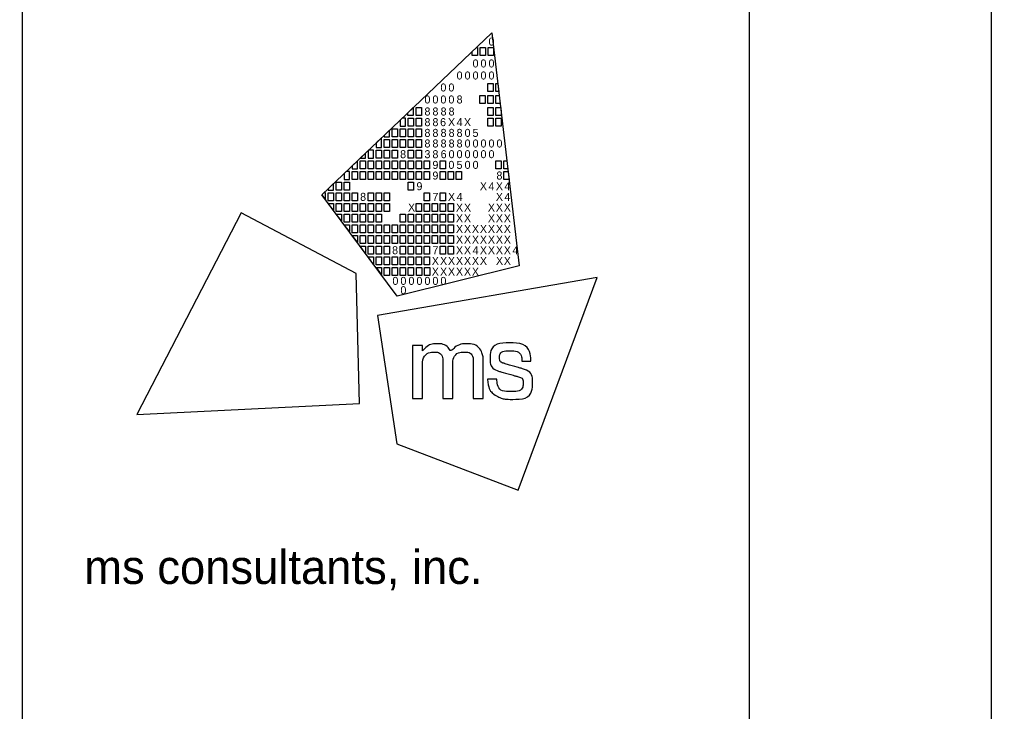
# Model space of a CAD drawing. Extents: x 0 to 34, y 0 to 22.
# Drawn here: x 31.994 to 34, y 2.686 to 4.114 of the extents above; entities that cross this region are included whole.
import ezdxf

# ---------------------------------------------------------------- set-up
doc = ezdxf.new("R2010")
doc.units = 0
for name, color, linetype in [('SH_Border', 7, 'Continuous'), ('SH_Cut_Line', 7, 'Continuous'), ('SH_Data', 7, 'Continuous')]:
    doc.layers.add(name, color=color, linetype=linetype)

msp = doc.modelspace()

# ---------------------------------------------------------------- linework, layer by layer
at = {"layer": 'SH_Border'}
msp.add_line((32, 0.5), (32, 21.5), dxfattribs=at)
msp.add_lwpolyline([(1.5, 21.5), (33.5, 21.5), (33.5, 0.5), (1.5, 0.5)], close=True, dxfattribs=at)
at = {"layer": 'SH_Cut_Line'}
msp.add_lwpolyline([(0, 0), (34, 0), (34, 22), (0, 22)], close=True, dxfattribs=at)
at = {"layer": 'SH_Data'}
for p, q in [((32.6175, 3.7519), (32.9688, 4.0861)), ((32.9688, 4.0861), (32.9688, 4.0861)), ((32.9688, 4.0861), (33.0253, 3.6052)), ((32.773, 3.543), (32.6175, 3.7519)), ((33.0253, 3.6052), (32.773, 3.543)), ((32.75, 3.5), (32.75, 3.5))]:
    msp.add_line(p, q, dxfattribs=at)
for points in [[(32.9279, 4.0472), (32.9369, 4.0558), (32.9389, 4.0558), (32.9389, 4.0393), (32.9279, 4.0393)], [(32.9444, 4.0558), (32.9554, 4.0558), (32.9554, 4.0393), (32.9444, 4.0393)], [(32.9609, 4.0558), (32.9719, 4.0558), (32.9719, 4.0393), (32.9609, 4.0393)], [(32.9606, 3.9815), (32.9716, 3.9815), (32.9716, 3.965), (32.9606, 3.965)], [(32.9771, 3.9815), (32.9811, 3.9815), (32.983, 3.965), (32.9771, 3.965)], [(32.9441, 3.9567), (32.9551, 3.9567), (32.9551, 3.9402), (32.9441, 3.9402)], [(32.9606, 3.9567), (32.9716, 3.9567), (32.9716, 3.9402), (32.9606, 3.9402)], [(32.9771, 3.9567), (32.984, 3.9567), (32.9859, 3.9402), (32.9771, 3.9402)], [(32.7953, 3.9211), (32.8064, 3.9316), (32.8064, 3.9154), (32.7953, 3.9154)], [(32.8123, 3.9319), (32.8233, 3.9319), (32.8233, 3.9154), (32.8123, 3.9154)], [(32.9606, 3.9319), (32.9716, 3.9319), (32.9716, 3.9154), (32.9606, 3.9154)], [(32.9771, 3.9319), (32.9869, 3.9319), (32.9881, 3.9218), (32.9881, 3.9154), (32.9771, 3.9154)], [(32.7958, 3.9099), (32.8068, 3.9099), (32.8068, 3.8934), (32.7958, 3.8934)], [(32.8123, 3.9099), (32.8233, 3.9099), (32.8233, 3.8934), (32.8123, 3.8934)], [(32.9606, 3.9099), (32.9716, 3.9099), (32.9716, 3.8934), (32.9606, 3.8934)], [(32.9771, 3.9099), (32.9881, 3.9099), (32.9881, 3.8934), (32.9771, 3.8934)], [(32.7627, 3.8879), (32.7737, 3.8879), (32.7737, 3.8714), (32.7627, 3.8714)], [(32.7793, 3.8879), (32.7903, 3.8879), (32.7903, 3.8714), (32.7793, 3.8714)], [(32.7958, 3.8879), (32.8068, 3.8879), (32.8068, 3.8714), (32.7958, 3.8714)], [(32.8123, 3.8879), (32.8233, 3.8879), (32.8233, 3.8714), (32.8123, 3.8714)], [(32.7462, 3.8659), (32.7572, 3.8659), (32.7572, 3.8494), (32.7462, 3.8494)], [(32.7627, 3.8659), (32.7737, 3.8659), (32.7737, 3.8494), (32.7627, 3.8494)], [(32.7793, 3.8659), (32.7903, 3.8659), (32.7903, 3.8494), (32.7793, 3.8494)], [(32.7958, 3.8659), (32.8068, 3.8659), (32.8068, 3.8494), (32.7958, 3.8494)], [(32.8123, 3.8659), (32.8233, 3.8659), (32.8233, 3.8494), (32.8123, 3.8494)], [(32.7297, 3.8439), (32.7407, 3.8439), (32.7407, 3.8273), (32.7297, 3.8273)], [(32.7462, 3.8439), (32.7572, 3.8439), (32.7572, 3.8273), (32.7462, 3.8273)], [(32.7627, 3.8439), (32.7737, 3.8439), (32.7737, 3.8273), (32.7627, 3.8273)], [(32.7958, 3.8439), (32.8068, 3.8439), (32.8068, 3.8273), (32.7958, 3.8273)], [(32.8123, 3.8439), (32.8233, 3.8439), (32.8233, 3.8273), (32.8123, 3.8273)], [(32.6967, 3.8218), (32.7077, 3.8218), (32.7077, 3.8053), (32.6967, 3.8053)], [(32.7132, 3.8218), (32.7242, 3.8218), (32.7242, 3.8053), (32.7132, 3.8053)], [(32.7297, 3.8218), (32.7407, 3.8218), (32.7407, 3.8053), (32.7297, 3.8053)], [(32.7462, 3.8218), (32.7572, 3.8218), (32.7572, 3.8053), (32.7462, 3.8053)], [(32.7627, 3.8218), (32.7737, 3.8218), (32.7737, 3.8053), (32.7627, 3.8053)], [(32.7793, 3.8218), (32.7903, 3.8218), (32.7903, 3.8053), (32.7793, 3.8053)], [(32.7958, 3.8218), (32.8068, 3.8218), (32.8068, 3.8053), (32.7958, 3.8053)], [(32.8123, 3.8218), (32.8233, 3.8218), (32.8233, 3.8053), (32.8123, 3.8053)], [(32.8288, 3.8218), (32.8398, 3.8218), (32.8398, 3.8053), (32.8288, 3.8053)], [(32.8618, 3.8218), (32.8728, 3.8218), (32.8728, 3.8053), (32.8618, 3.8053)], [(32.9771, 3.8218), (32.9881, 3.8218), (32.9881, 3.8053), (32.9771, 3.8053)], [(32.9935, 3.8218), (32.9998, 3.8218), (33.0018, 3.8053), (32.9935, 3.8053)], [(32.6802, 3.7998), (32.6912, 3.7998), (32.6912, 3.7833), (32.6802, 3.7833)], [(32.6967, 3.7998), (32.7077, 3.7998), (32.7077, 3.7833), (32.6967, 3.7833)], [(32.7132, 3.7998), (32.7242, 3.7998), (32.7242, 3.7833), (32.7132, 3.7833)], [(32.7297, 3.7998), (32.7407, 3.7998), (32.7407, 3.7833), (32.7297, 3.7833)], [(32.7462, 3.7998), (32.7572, 3.7998), (32.7572, 3.7833), (32.7462, 3.7833)], [(32.7627, 3.7998), (32.7737, 3.7998), (32.7737, 3.7833), (32.7627, 3.7833)], [(32.7793, 3.7998), (32.7903, 3.7998), (32.7903, 3.7833), (32.7793, 3.7833)], [(32.7958, 3.7998), (32.8068, 3.7998), (32.8068, 3.7833), (32.7958, 3.7833)], [(32.8123, 3.7998), (32.8233, 3.7998), (32.8233, 3.7833), (32.8123, 3.7833)], [(32.8288, 3.7998), (32.8398, 3.7998), (32.8398, 3.7833), (32.8288, 3.7833)], [(32.8618, 3.7998), (32.8728, 3.7998), (32.8728, 3.7833), (32.8618, 3.7833)], [(32.8783, 3.7998), (32.8893, 3.7998), (32.8893, 3.7833), (32.8783, 3.7833)], [(32.8947, 3.7998), (32.9057, 3.7998), (32.9057, 3.7833), (32.8947, 3.7833)], [(32.9935, 3.7998), (33.0024, 3.7998), (33.0044, 3.7833), (32.9935, 3.7833)], [(32.6471, 3.7778), (32.6581, 3.7778), (32.6581, 3.7613), (32.6471, 3.7613)], [(32.6637, 3.7778), (32.6747, 3.7778), (32.6747, 3.7613), (32.6637, 3.7613)], [(32.7958, 3.7778), (32.8068, 3.7778), (32.8068, 3.7613), (32.7958, 3.7613)], [(32.6306, 3.7558), (32.6416, 3.7558), (32.6416, 3.7393), (32.6306, 3.7393)], [(32.6471, 3.7558), (32.6581, 3.7558), (32.6581, 3.7393), (32.6471, 3.7393)], [(32.6637, 3.7558), (32.6747, 3.7558), (32.6747, 3.7393), (32.6637, 3.7393)], [(32.6802, 3.7558), (32.6912, 3.7558), (32.6912, 3.7393), (32.6802, 3.7393)], [(32.7132, 3.7558), (32.7242, 3.7558), (32.7242, 3.7393), (32.7132, 3.7393)], [(32.7297, 3.7558), (32.7407, 3.7558), (32.7407, 3.7393), (32.7297, 3.7393)], [(32.7462, 3.7558), (32.7572, 3.7558), (32.7572, 3.7393), (32.7462, 3.7393)], [(32.8288, 3.7558), (32.8398, 3.7558), (32.8398, 3.7393), (32.8288, 3.7393)], [(32.8618, 3.7558), (32.8728, 3.7558), (32.8728, 3.7393), (32.8618, 3.7393)], [(32.6306, 3.7338), (32.6416, 3.7338), (32.6416, 3.72)], [(32.6471, 3.7338), (32.6581, 3.7338), (32.6581, 3.7173), (32.6471, 3.7173)], [(32.6637, 3.7338), (32.6747, 3.7338), (32.6747, 3.7173), (32.6637, 3.7173)], [(32.6802, 3.7338), (32.6912, 3.7338), (32.6912, 3.7173), (32.6802, 3.7173)], [(32.6967, 3.7338), (32.7077, 3.7338), (32.7077, 3.7173), (32.6967, 3.7173)], [(32.7132, 3.7338), (32.7242, 3.7338), (32.7242, 3.7173), (32.7132, 3.7173)], [(32.7297, 3.7338), (32.7407, 3.7338), (32.7407, 3.7173), (32.7297, 3.7173)], [(32.7462, 3.7338), (32.7572, 3.7338), (32.7572, 3.7173), (32.7462, 3.7173)], [(32.8123, 3.7338), (32.8233, 3.7338), (32.8233, 3.7173), (32.8123, 3.7173)], [(32.8288, 3.7338), (32.8398, 3.7338), (32.8398, 3.7173), (32.8288, 3.7173)], [(32.8453, 3.7338), (32.8563, 3.7338), (32.8563, 3.7173), (32.8453, 3.7173)], [(32.8618, 3.7338), (32.8728, 3.7338), (32.8728, 3.7173), (32.8618, 3.7173)], [(32.8783, 3.7338), (32.8893, 3.7338), (32.8893, 3.7173), (32.8783, 3.7173)], [(32.6471, 3.7117), (32.6581, 3.7117), (32.6581, 3.698)], [(32.6637, 3.7117), (32.6747, 3.7117), (32.6747, 3.6952), (32.6637, 3.6952)], [(32.6802, 3.7117), (32.6912, 3.7117), (32.6912, 3.6952), (32.6802, 3.6952)], [(32.6967, 3.7117), (32.7077, 3.7117), (32.7077, 3.6952), (32.6967, 3.6952)], [(32.7132, 3.7117), (32.7242, 3.7117), (32.7242, 3.6952), (32.7132, 3.6952)], [(32.7297, 3.7117), (32.7407, 3.7117), (32.7407, 3.6952), (32.7297, 3.6952)], [(32.7793, 3.7117), (32.7903, 3.7117), (32.7903, 3.6952), (32.7793, 3.6952)], [(32.7958, 3.7117), (32.8068, 3.7117), (32.8068, 3.6952), (32.7958, 3.6952)], [(32.8123, 3.7117), (32.8233, 3.7117), (32.8233, 3.6952), (32.8123, 3.6952)], [(32.8288, 3.7117), (32.8398, 3.7117), (32.8398, 3.6952), (32.8288, 3.6952)], [(32.8453, 3.7117), (32.8563, 3.7117), (32.8563, 3.6952), (32.8453, 3.6952)], [(32.8618, 3.7117), (32.8728, 3.7117), (32.8728, 3.6952), (32.8618, 3.6952)], [(32.8783, 3.7117), (32.8893, 3.7117), (32.8893, 3.6952), (32.8783, 3.6952)], [(32.6637, 3.6897), (32.6747, 3.6897), (32.6747, 3.676)], [(32.6747, 3.6897), (32.6747, 3.6897), (32.6747, 3.6897)], [(32.6802, 3.6897), (32.6912, 3.6897), (32.6912, 3.6732), (32.6802, 3.6732)], [(32.6967, 3.6897), (32.7077, 3.6897), (32.7077, 3.6732), (32.6967, 3.6732)], [(32.7132, 3.6897), (32.7242, 3.6897), (32.7242, 3.6732), (32.7132, 3.6732)], [(32.7297, 3.6897), (32.7407, 3.6897), (32.7407, 3.6732), (32.7297, 3.6732)], [(32.7462, 3.6897), (32.7572, 3.6897), (32.7572, 3.6732), (32.7462, 3.6732)], [(32.7627, 3.6897), (32.7737, 3.6897), (32.7737, 3.6732), (32.7627, 3.6732)], [(32.7793, 3.6897), (32.7903, 3.6897), (32.7903, 3.6732), (32.7793, 3.6732)], [(32.7958, 3.6897), (32.8068, 3.6897), (32.8068, 3.6732), (32.7958, 3.6732)], [(32.8123, 3.6897), (32.8233, 3.6897), (32.8233, 3.6732), (32.8123, 3.6732)], [(32.8288, 3.6897), (32.8398, 3.6897), (32.8398, 3.6732), (32.8288, 3.6732)], [(32.8453, 3.6897), (32.8563, 3.6897), (32.8563, 3.6732), (32.8453, 3.6732)], [(32.8618, 3.6897), (32.8728, 3.6897), (32.8728, 3.6732), (32.8618, 3.6732)], [(32.8783, 3.6897), (32.8893, 3.6897), (32.8893, 3.6732), (32.8783, 3.6732)], [(32.6802, 3.6677), (32.6912, 3.6677), (32.6912, 3.654)], [(32.6967, 3.6677), (32.7077, 3.6677), (32.7077, 3.6512), (32.6967, 3.6512)], [(32.7132, 3.6677), (32.7242, 3.6677), (32.7242, 3.6512), (32.7132, 3.6512)], [(32.7297, 3.6677), (32.7407, 3.6677), (32.7407, 3.6512), (32.7297, 3.6512)], [(32.7462, 3.6677), (32.7572, 3.6677), (32.7572, 3.6512), (32.7462, 3.6512)], [(32.7627, 3.6677), (32.7737, 3.6677), (32.7737, 3.6512), (32.7627, 3.6512)], [(32.7793, 3.6677), (32.7903, 3.6677), (32.7903, 3.6512), (32.7793, 3.6512)], [(32.7958, 3.6677), (32.8068, 3.6677), (32.8068, 3.6512), (32.7958, 3.6512)], [(32.8123, 3.6677), (32.8233, 3.6677), (32.8233, 3.6512), (32.8123, 3.6512)], [(32.8288, 3.6677), (32.8398, 3.6677), (32.8398, 3.6512), (32.8288, 3.6512)], [(32.8453, 3.6677), (32.8563, 3.6677), (32.8563, 3.6512), (32.8453, 3.6512)], [(32.8618, 3.6677), (32.8728, 3.6677), (32.8728, 3.6512), (32.8618, 3.6512)], [(32.8783, 3.6677), (32.8893, 3.6677), (32.8893, 3.6512), (32.8783, 3.6512)], [(32.7077, 3.6305), (32.6965, 3.6457), (32.7077, 3.6457)], [(32.7132, 3.6457), (32.7242, 3.6457), (32.7242, 3.6292), (32.7132, 3.6292)], [(32.7297, 3.6457), (32.7407, 3.6457), (32.7407, 3.6292), (32.7297, 3.6292)], [(32.7462, 3.6457), (32.7572, 3.6457), (32.7572, 3.6292), (32.7462, 3.6292)], [(32.7793, 3.6457), (32.7903, 3.6457), (32.7903, 3.6292), (32.7793, 3.6292)], [(32.7958, 3.6457), (32.8068, 3.6457), (32.8068, 3.6292), (32.7958, 3.6292)], [(32.8123, 3.6457), (32.8233, 3.6457), (32.8233, 3.6292), (32.8123, 3.6292)], [(32.8288, 3.6457), (32.8398, 3.6457), (32.8398, 3.6292), (32.8288, 3.6292)], [(32.8618, 3.6457), (32.8728, 3.6457), (32.8728, 3.6292), (32.8618, 3.6292)], [(32.8783, 3.6457), (32.8893, 3.6457), (32.8893, 3.6292), (32.8783, 3.6292)], [(32.724, 3.6082), (32.7132, 3.6237), (32.7242, 3.6237)], [(32.7297, 3.6237), (32.7407, 3.6237), (32.7407, 3.6072), (32.7297, 3.6072)], [(32.7462, 3.6237), (32.7572, 3.6237), (32.7572, 3.6072), (32.7462, 3.6072)], [(32.7627, 3.6237), (32.7737, 3.6237), (32.7737, 3.6072), (32.7627, 3.6072)], [(32.7793, 3.6237), (32.7903, 3.6237), (32.7903, 3.6072), (32.7793, 3.6072)], [(32.7958, 3.6237), (32.8068, 3.6237), (32.8068, 3.6072), (32.7958, 3.6072)], [(32.8123, 3.6237), (32.8233, 3.6237), (32.8233, 3.6072), (32.8123, 3.6072)], [(32.8288, 3.6237), (32.8398, 3.6237), (32.8398, 3.6072), (32.8288, 3.6072)], [(32.7302, 3.6017), (32.7407, 3.6017), (32.7408, 3.5875)], [(32.7463, 3.6017), (32.7573, 3.6017), (32.7573, 3.5852), (32.7463, 3.5852)], [(32.763, 3.6017), (32.774, 3.6017), (32.774, 3.5852), (32.763, 3.5852)], [(32.7794, 3.6017), (32.7904, 3.6017), (32.7904, 3.5852), (32.7794, 3.5852)], [(32.796, 3.6017), (32.807, 3.6017), (32.807, 3.5852), (32.796, 3.5852)], [(32.8129, 3.6017), (32.8239, 3.6017), (32.8239, 3.5851), (32.8129, 3.5851)], [(32.8296, 3.6017), (32.8406, 3.6017), (32.8406, 3.5851), (32.8296, 3.5851)]]:
    msp.add_lwpolyline(points, close=True, dxfattribs=at)
for points in [[(32.7903, 3.9099), (32.7836, 3.9099), (32.7793, 3.9058), (32.7793, 3.8934), (32.7903, 3.8934), (32.7903, 3.9099)], [(32.7572, 3.8849), (32.7462, 3.8744), (32.7462, 3.8714), (32.7572, 3.8714), (32.7572, 3.8849)], [(32.7407, 3.8691), (32.7297, 3.8587), (32.7297, 3.8494), (32.7407, 3.8494), (32.7407, 3.8691)], [(32.7077, 3.8377), (32.6968, 3.8273), (32.7077, 3.8273), (32.7077, 3.8377)], [(32.7242, 3.8439), (32.7141, 3.8439), (32.7132, 3.843), (32.7132, 3.8273), (32.7242, 3.8273), (32.7242, 3.8439)], [(32.6912, 3.822), (32.6802, 3.8115), (32.6802, 3.8053), (32.6912, 3.8053), (32.6912, 3.822)], [(32.6747, 3.7998), (32.6679, 3.7998), (32.6637, 3.7958), (32.6637, 3.7833), (32.6747, 3.7833), (32.6747, 3.7998)], [(32.6416, 3.7749), (32.6306, 3.7644), (32.6306, 3.7613), (32.6416, 3.7613), (32.6416, 3.7749)], [(32.6251, 3.7558), (32.6216, 3.7558), (32.6175, 3.7519), (32.6251, 3.7417), (32.6251, 3.7558)], [(32.4512, 3.7149), (32.2359, 3.2988), (32.6956, 3.3215), (32.6884, 3.5892), (32.4512, 3.7149)], [(33.0229, 3.1422), (33.1859, 3.5814), (32.7324, 3.5029), (32.7722, 3.2381), (33.0229, 3.1422)]]:
    msp.add_lwpolyline(points, dxfattribs=at)
for points in [[(32.8048, 3.3315), (32.8048, 3.3315), (32.8048, 3.4409), (32.8048, 3.4409), (32.8048, 3.4409), (32.8255, 3.4409), (32.8255, 3.4409), (32.8255, 3.4409), (32.8255, 3.4297), (32.8255, 3.4297), (32.8346, 3.4399), (32.8457, 3.4445), (32.8555, 3.4445), (32.8688, 3.4445), (32.8791, 3.4372), (32.8837, 3.4266), (32.8915, 3.4381), (32.905, 3.4446), (32.9166, 3.4446), (32.9325, 3.4446), (32.9451, 3.435), (32.9494, 3.4213), (32.9494, 3.4212), (32.9494, 3.4212), (32.9494, 3.4212), (32.9501, 3.419), (32.9506, 3.4172), (32.9506, 3.4071), (32.9506, 3.4071), (32.9506, 3.3314), (32.9506, 3.3314), (32.9506, 3.3314), (32.9303, 3.3314), (32.9303, 3.3314), (32.9303, 3.3314), (32.9303, 3.4048), (32.9303, 3.4048), (32.9303, 3.4201), (32.9219, 3.4274), (32.911, 3.4274), (32.8995, 3.4274), (32.8879, 3.4171), (32.8879, 3.4001), (32.8879, 3.4001), (32.8879, 3.3315), (32.8879, 3.3315), (32.8879, 3.3315), (32.8674, 3.3315), (32.8674, 3.3315), (32.8674, 3.3315), (32.8674, 3.4059), (32.8674, 3.4059), (32.8674, 3.4203), (32.8588, 3.4274), (32.8496, 3.4274), (32.8384, 3.4274), (32.8254, 3.417), (32.8254, 3.3962), (32.8254, 3.3962), (32.8254, 3.3315), (32.8254, 3.3315), (32.8254, 3.3315), (32.8048, 3.3315), (32.8048, 3.3315)], [(32.9595, 3.3709), (32.9595, 3.3709), (32.9595, 3.3717), (32.9595, 3.3717), (32.9595, 3.3717), (32.9603, 3.3717), (32.9603, 3.3717), (32.9603, 3.3717), (32.9783, 3.3717), (32.9783, 3.3717), (32.9783, 3.3717), (32.9789, 3.3717), (32.9789, 3.3717), (32.9789, 3.3717), (32.979, 3.371), (32.979, 3.371), (32.9803, 3.3554), (32.9887, 3.346), (33.009, 3.346), (33.0273, 3.346), (33.0333, 3.3554), (33.0333, 3.3631), (33.0333, 3.3732), (33.0256, 3.3758), (33.0175, 3.378), (33.0175, 3.378), (32.987, 3.3867), (32.987, 3.3867), (32.972, 3.3909), (32.9648, 3.4019), (32.9648, 3.4142), (32.9648, 3.4303), (32.9768, 3.4462), (33.0052, 3.4462), (33.0348, 3.4462), (33.0489, 3.4285), (33.0489, 3.4095), (33.0489, 3.4095), (33.0489, 3.4087), (33.0489, 3.4087), (33.0489, 3.4087), (33.0482, 3.4087), (33.0482, 3.4087), (33.0482, 3.4087), (33.0312, 3.4087), (33.0312, 3.4087), (33.0312, 3.4087), (33.0305, 3.4087), (33.0305, 3.4087), (33.0305, 3.4087), (33.0305, 3.4094), (33.0305, 3.4094), (33.0301, 3.4208), (33.0226, 3.43), (33.0056, 3.43), (32.9891, 3.43), (32.9843, 3.4218), (32.9843, 3.4157), (32.9843, 3.4108), (32.9869, 3.4059), (32.9959, 3.4033), (32.9959, 3.4033), (33.0255, 3.3948), (33.0255, 3.3948), (33.0462, 3.3889), (33.0527, 3.3777), (33.0527, 3.3639), (33.0527, 3.3462), (33.041, 3.3298), (33.0087, 3.3298), (32.9952, 3.3298), (32.9877, 3.3321), (32.9823, 3.3348), (32.969, 3.3414), (32.9609, 3.3536), (32.9595, 3.3709)]]:
    msp.add_open_spline(points, degree=3, dxfattribs=at)

# ---------------------------------------------------------------- texts
for s, height, p in [('0', 0.0165, (32.9617, 4.0597)), ('0', 0.0165, (32.9288, 4.0145)), ('0', 0.0165, (32.9452, 4.0145)), ('0', 0.0165, (32.9617, 4.0145)), ('0', 0.0165, (32.8958, 3.9897)), ('0', 0.0165, (32.9123, 3.9897)), ('0', 0.0165, (32.9288, 3.9897)), ('0', 0.0165, (32.9452, 3.9897)), ('0', 0.0165, (32.9617, 3.9897)), ('0', 0.0165, (32.8625, 3.965)), ('0', 0.0165, (32.879, 3.965)), ('0', 0.0165, (32.8295, 3.9402)), ('0', 0.0165, (32.846, 3.9402)), ('0', 0.0165, (32.8625, 3.9402)), ('0', 0.0165, (32.879, 3.9402)), ('8', 0.0165, (32.8958, 3.9402)), ('8', 0.0165, (32.8295, 3.9154)), ('8', 0.0165, (32.846, 3.9154)), ('8', 0.0165, (32.8628, 3.9154)), ('8', 0.0165, (32.8793, 3.9154)), ('8', 0.0165, (32.8295, 3.8934)), ('8', 0.0165, (32.846, 3.8934)), ('6', 0.0165, (32.8618, 3.8934)), ('X', 0.0165, (32.8781, 3.8934)), ('4', 0.0165, (32.8958, 3.8934)), ('X', 0.0165, (32.911, 3.8934)), ('8', 0.0165, (32.8295, 3.8713)), ('8', 0.0165, (32.846, 3.8713)), ('8', 0.0165, (32.8628, 3.8713)), ('8', 0.0165, (32.8794, 3.8713)), ('8', 0.0165, (32.8958, 3.8713)), ('0', 0.0165, (32.9123, 3.8713)), ('5', 0.0165, (32.9287, 3.8713)), ('8', 0.0165, (32.8295, 3.8494)), ('8', 0.0165, (32.846, 3.8494)), ('8', 0.0165, (32.8628, 3.8494)), ('8', 0.0165, (32.8794, 3.8494)), ('8', 0.0165, (32.8958, 3.8494)), ('0', 0.0165, (32.9123, 3.8494)), ('0', 0.0165, (32.9288, 3.8494)), ('0', 0.0165, (32.9452, 3.8494)), ('0', 0.0165, (32.9617, 3.8494)), ('0', 0.0165, (32.9782, 3.8494)), ('8', 0.0165, (32.7793, 3.8273)), ('3', 0.0165, (32.8295, 3.8273)), ('8', 0.0165, (32.846, 3.8273)), ('6', 0.0165, (32.8629, 3.8273)), ('0', 0.0165, (32.8793, 3.8273)), ('0', 0.0165, (32.8958, 3.8273)), ('0', 0.0165, (32.9123, 3.8273)), ('0', 0.0165, (32.9288, 3.8273)), ('0', 0.0165, (32.9452, 3.8273)), ('0', 0.0165, (32.9617, 3.8273)), ('9', 0.0165, (32.846, 3.8053)), ('0', 0.0165, (32.879, 3.8053)), ('5', 0.0165, (32.8957, 3.8053)), ('0', 0.0165, (32.9123, 3.8053)), ('0', 0.0165, (32.9288, 3.8053)), ('9', 0.0165, (32.846, 3.7833)), ('8', 0.0165, (32.9781, 3.7833)), ('9', 0.0165, (32.813, 3.7613)), ('X', 0.0165, (32.9439, 3.7613)), ('4', 0.0165, (32.9617, 3.7613)), ('X', 0.0165, (32.9769, 3.7613)), ('4', 0.0165, (32.9946, 3.7613)), ('8', 0.0165, (32.6967, 3.7393)), ('7', 0.0165, (32.846, 3.7393)), ('X', 0.0165, (32.8781, 3.7393)), ('4', 0.0165, (32.8958, 3.7393)), ('X', 0.0165, (32.9769, 3.7393)), ('4', 0.0165, (32.9946, 3.7393)), ('X', 0.0165, (32.7955, 3.7173)), ('X', 0.0165, (32.8945, 3.7173)), ('X', 0.0165, (32.911, 3.7173)), ('X', 0.0165, (32.9604, 3.7173)), ('X', 0.0165, (32.9769, 3.7173)), ('X', 0.0165, (32.9933, 3.7173)), ('X', 0.0165, (32.8945, 3.6952)), ('X', 0.0165, (32.911, 3.6952)), ('X', 0.0165, (32.9604, 3.6952)), ('X', 0.0165, (32.9769, 3.6952)), ('X', 0.0165, (32.9933, 3.6952)), ('X', 0.0165, (32.8945, 3.6732)), ('X', 0.0165, (32.911, 3.6732)), ('X', 0.0165, (32.9274, 3.6732)), ('X', 0.0165, (32.9439, 3.6732)), ('X', 0.0165, (32.9604, 3.6732)), ('X', 0.0165, (32.9769, 3.6732)), ('X', 0.0165, (32.9933, 3.6732)), ('X', 0.0165, (32.8945, 3.6512)), ('X', 0.0165, (32.911, 3.6512)), ('X', 0.0165, (32.9274, 3.6512)), ('X', 0.0165, (32.9439, 3.6512)), ('X', 0.0165, (32.9604, 3.6512)), ('X', 0.0165, (32.9769, 3.6512)), ('X', 0.0165, (32.9933, 3.6512)), ('8', 0.0165, (32.7627, 3.6292)), ('7', 0.0165, (32.846, 3.6292)), ('X', 0.0165, (32.8945, 3.6292)), ('X', 0.0165, (32.911, 3.6292)), ('4', 0.0165, (32.9288, 3.6292)), ('X', 0.0165, (32.9439, 3.6292)), ('X', 0.0165, (32.9604, 3.6292)), ('X', 0.0165, (32.9769, 3.6292)), ('X', 0.0165, (32.9933, 3.6292)), ('4', 0.0165, (33.0111, 3.6292)), ('X', 0.0165, (32.8447, 3.6072)), ('X', 0.0165, (32.8616, 3.6072)), ('X', 0.0165, (32.878, 3.6072)), ('X', 0.0165, (32.8945, 3.6072)), ('X', 0.0165, (32.911, 3.6072)), ('X', 0.0165, (32.9274, 3.6072)), ('X', 0.0165, (32.9439, 3.6072)), ('X', 0.0165, (32.9771, 3.6072)), ('X', 0.0165, (32.9933, 3.6072)), ('X', 0.0165, (32.8447, 3.5851)), ('X', 0.0165, (32.8616, 3.5851)), ('X', 0.0165, (32.878, 3.5851)), ('X', 0.0165, (32.8945, 3.5851)), ('X', 0.0165, (32.911, 3.5851)), ('X', 0.0165, (32.9274, 3.5851)), ('0', 0.0165, (32.7634, 3.5659)), ('0', 0.0165, (32.7799, 3.5659)), ('0', 0.0165, (32.7965, 3.5659)), ('0', 0.0165, (32.813, 3.5659)), ('0', 0.0165, (32.8295, 3.5659)), ('0', 0.0165, (32.846, 3.5659)), ('0', 0.0165, (32.8625, 3.5659)), ('0', 0.0165, (32.7799, 3.5467)), ('ms consultants, inc.', 0.07, (32.1273, 2.9489))]:
    msp.add_text(s, height=height, rotation=360, dxfattribs=at).set_placement(p)

doc.saveas('drawing.dxf')
